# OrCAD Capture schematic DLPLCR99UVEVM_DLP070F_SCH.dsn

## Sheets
1 PG01 Title: size A3; rev: C
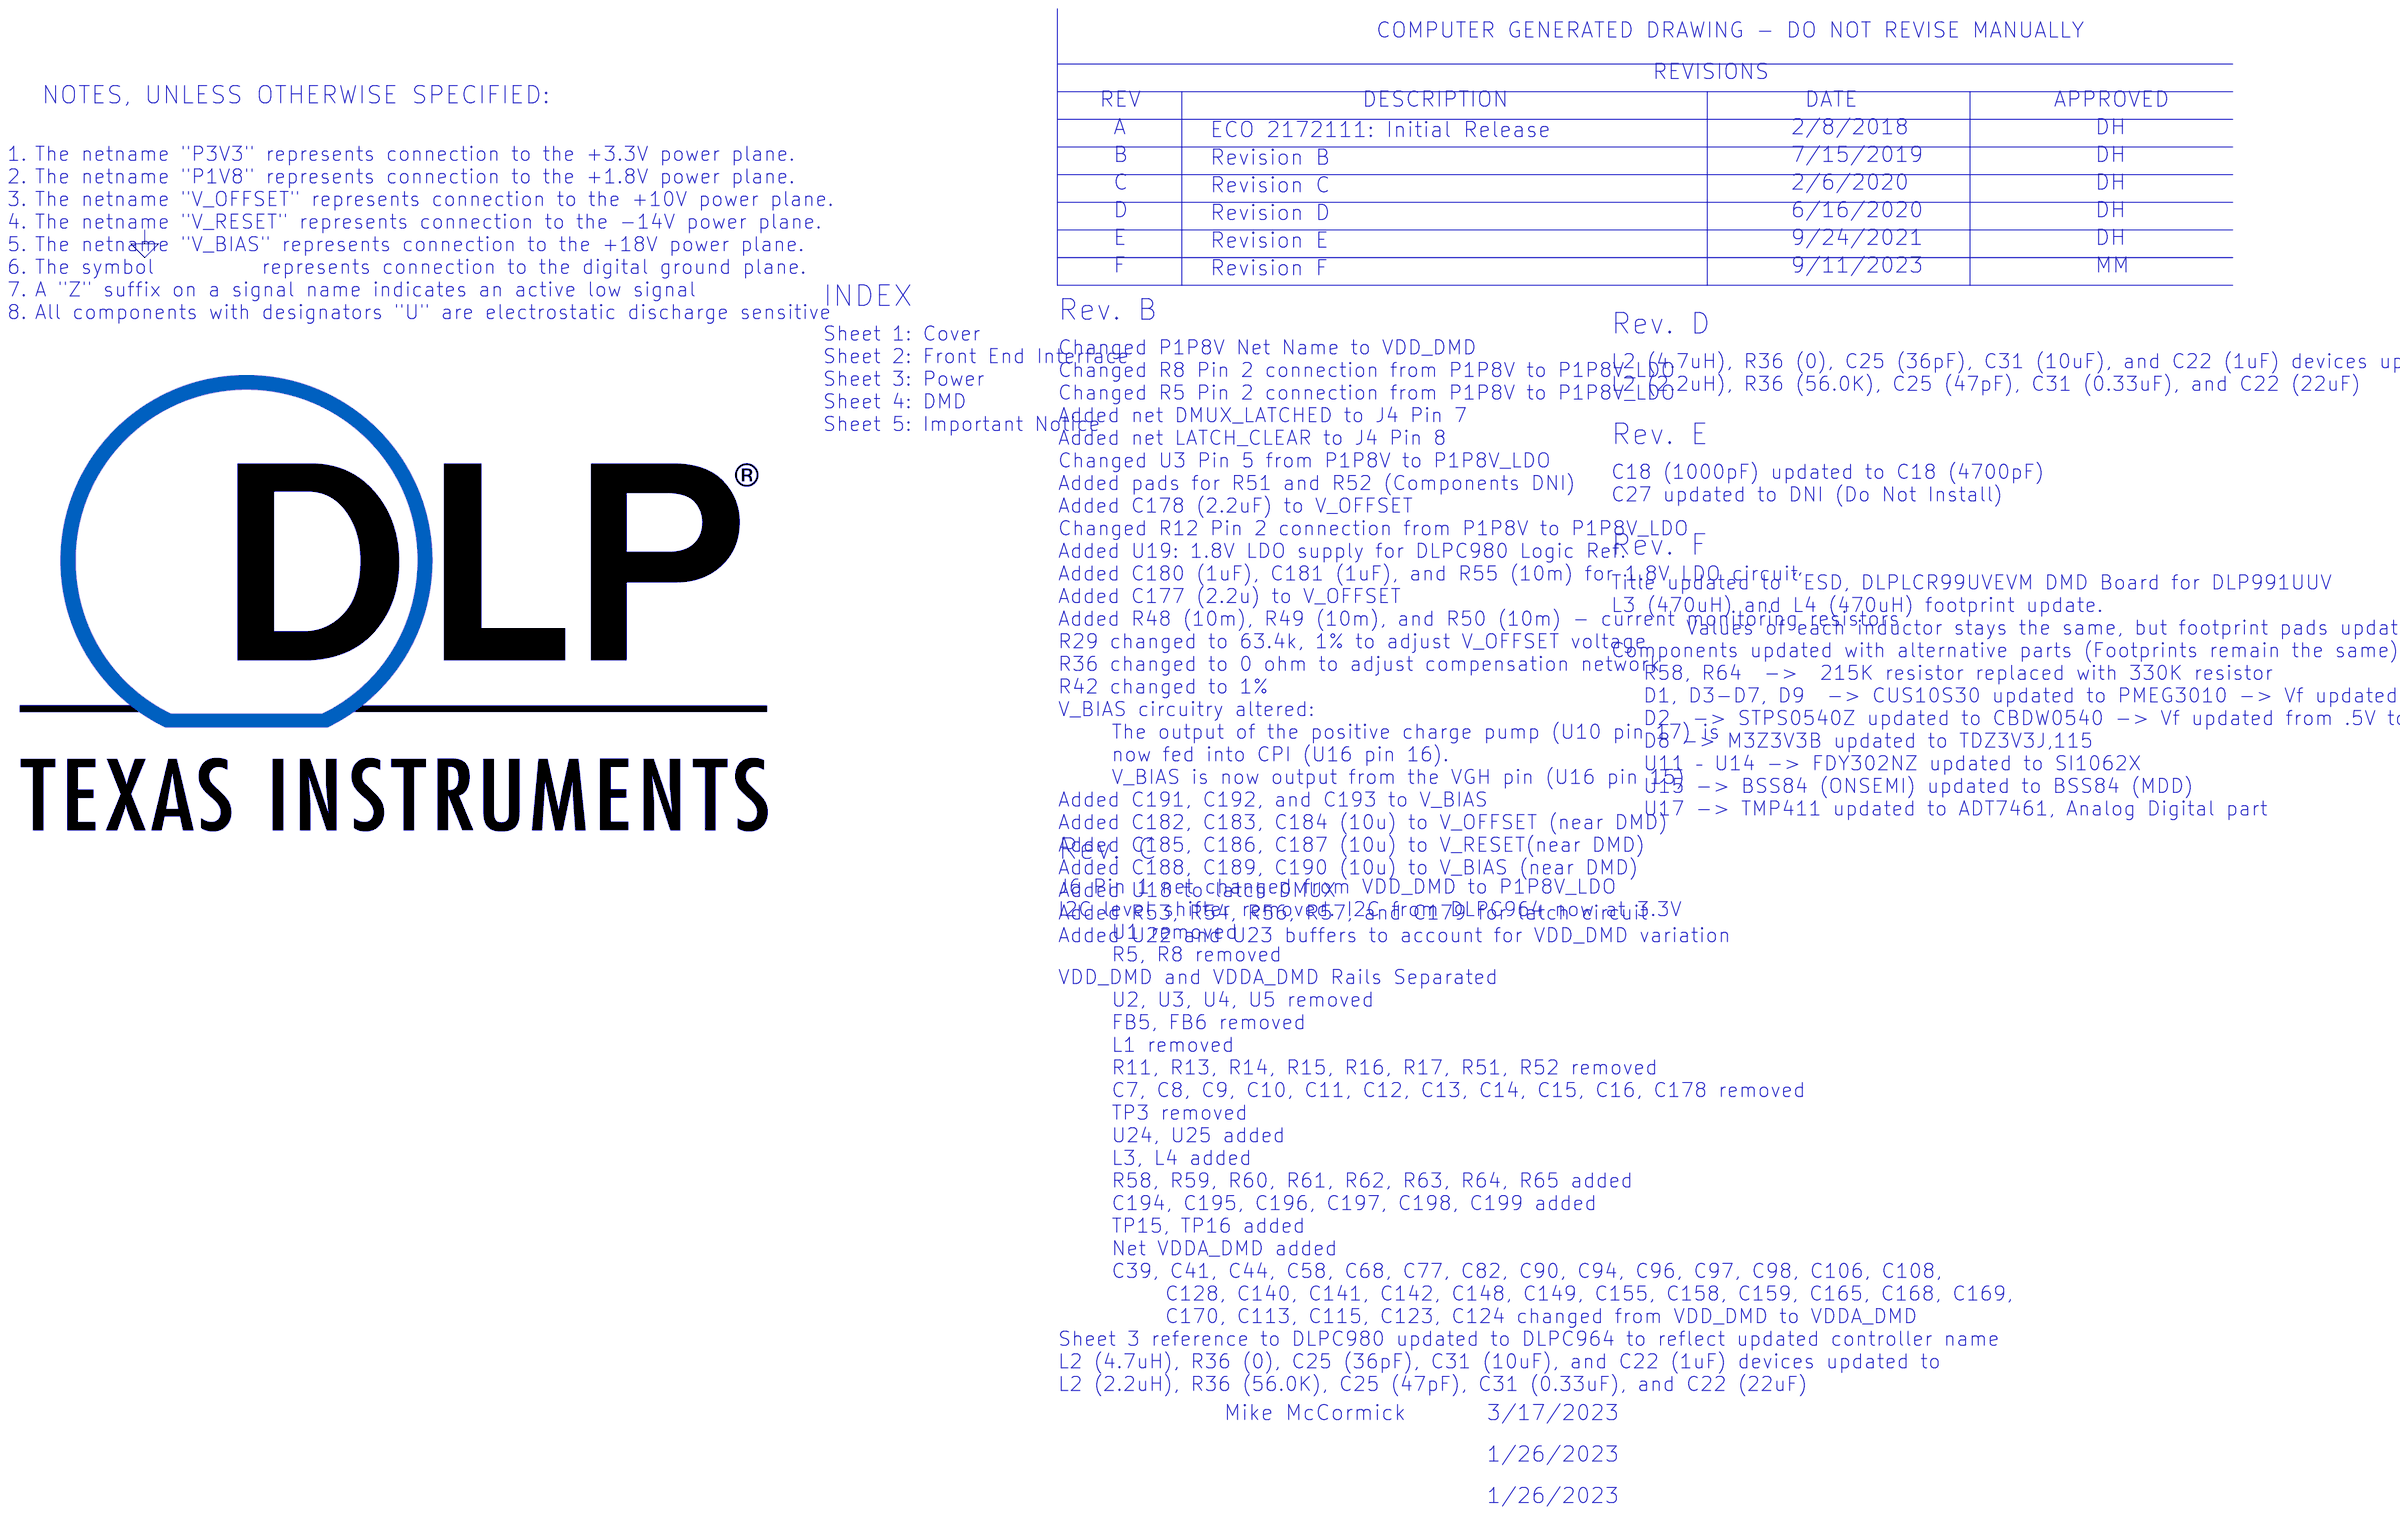
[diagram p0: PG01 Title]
2 PG02 Connectors: size A1
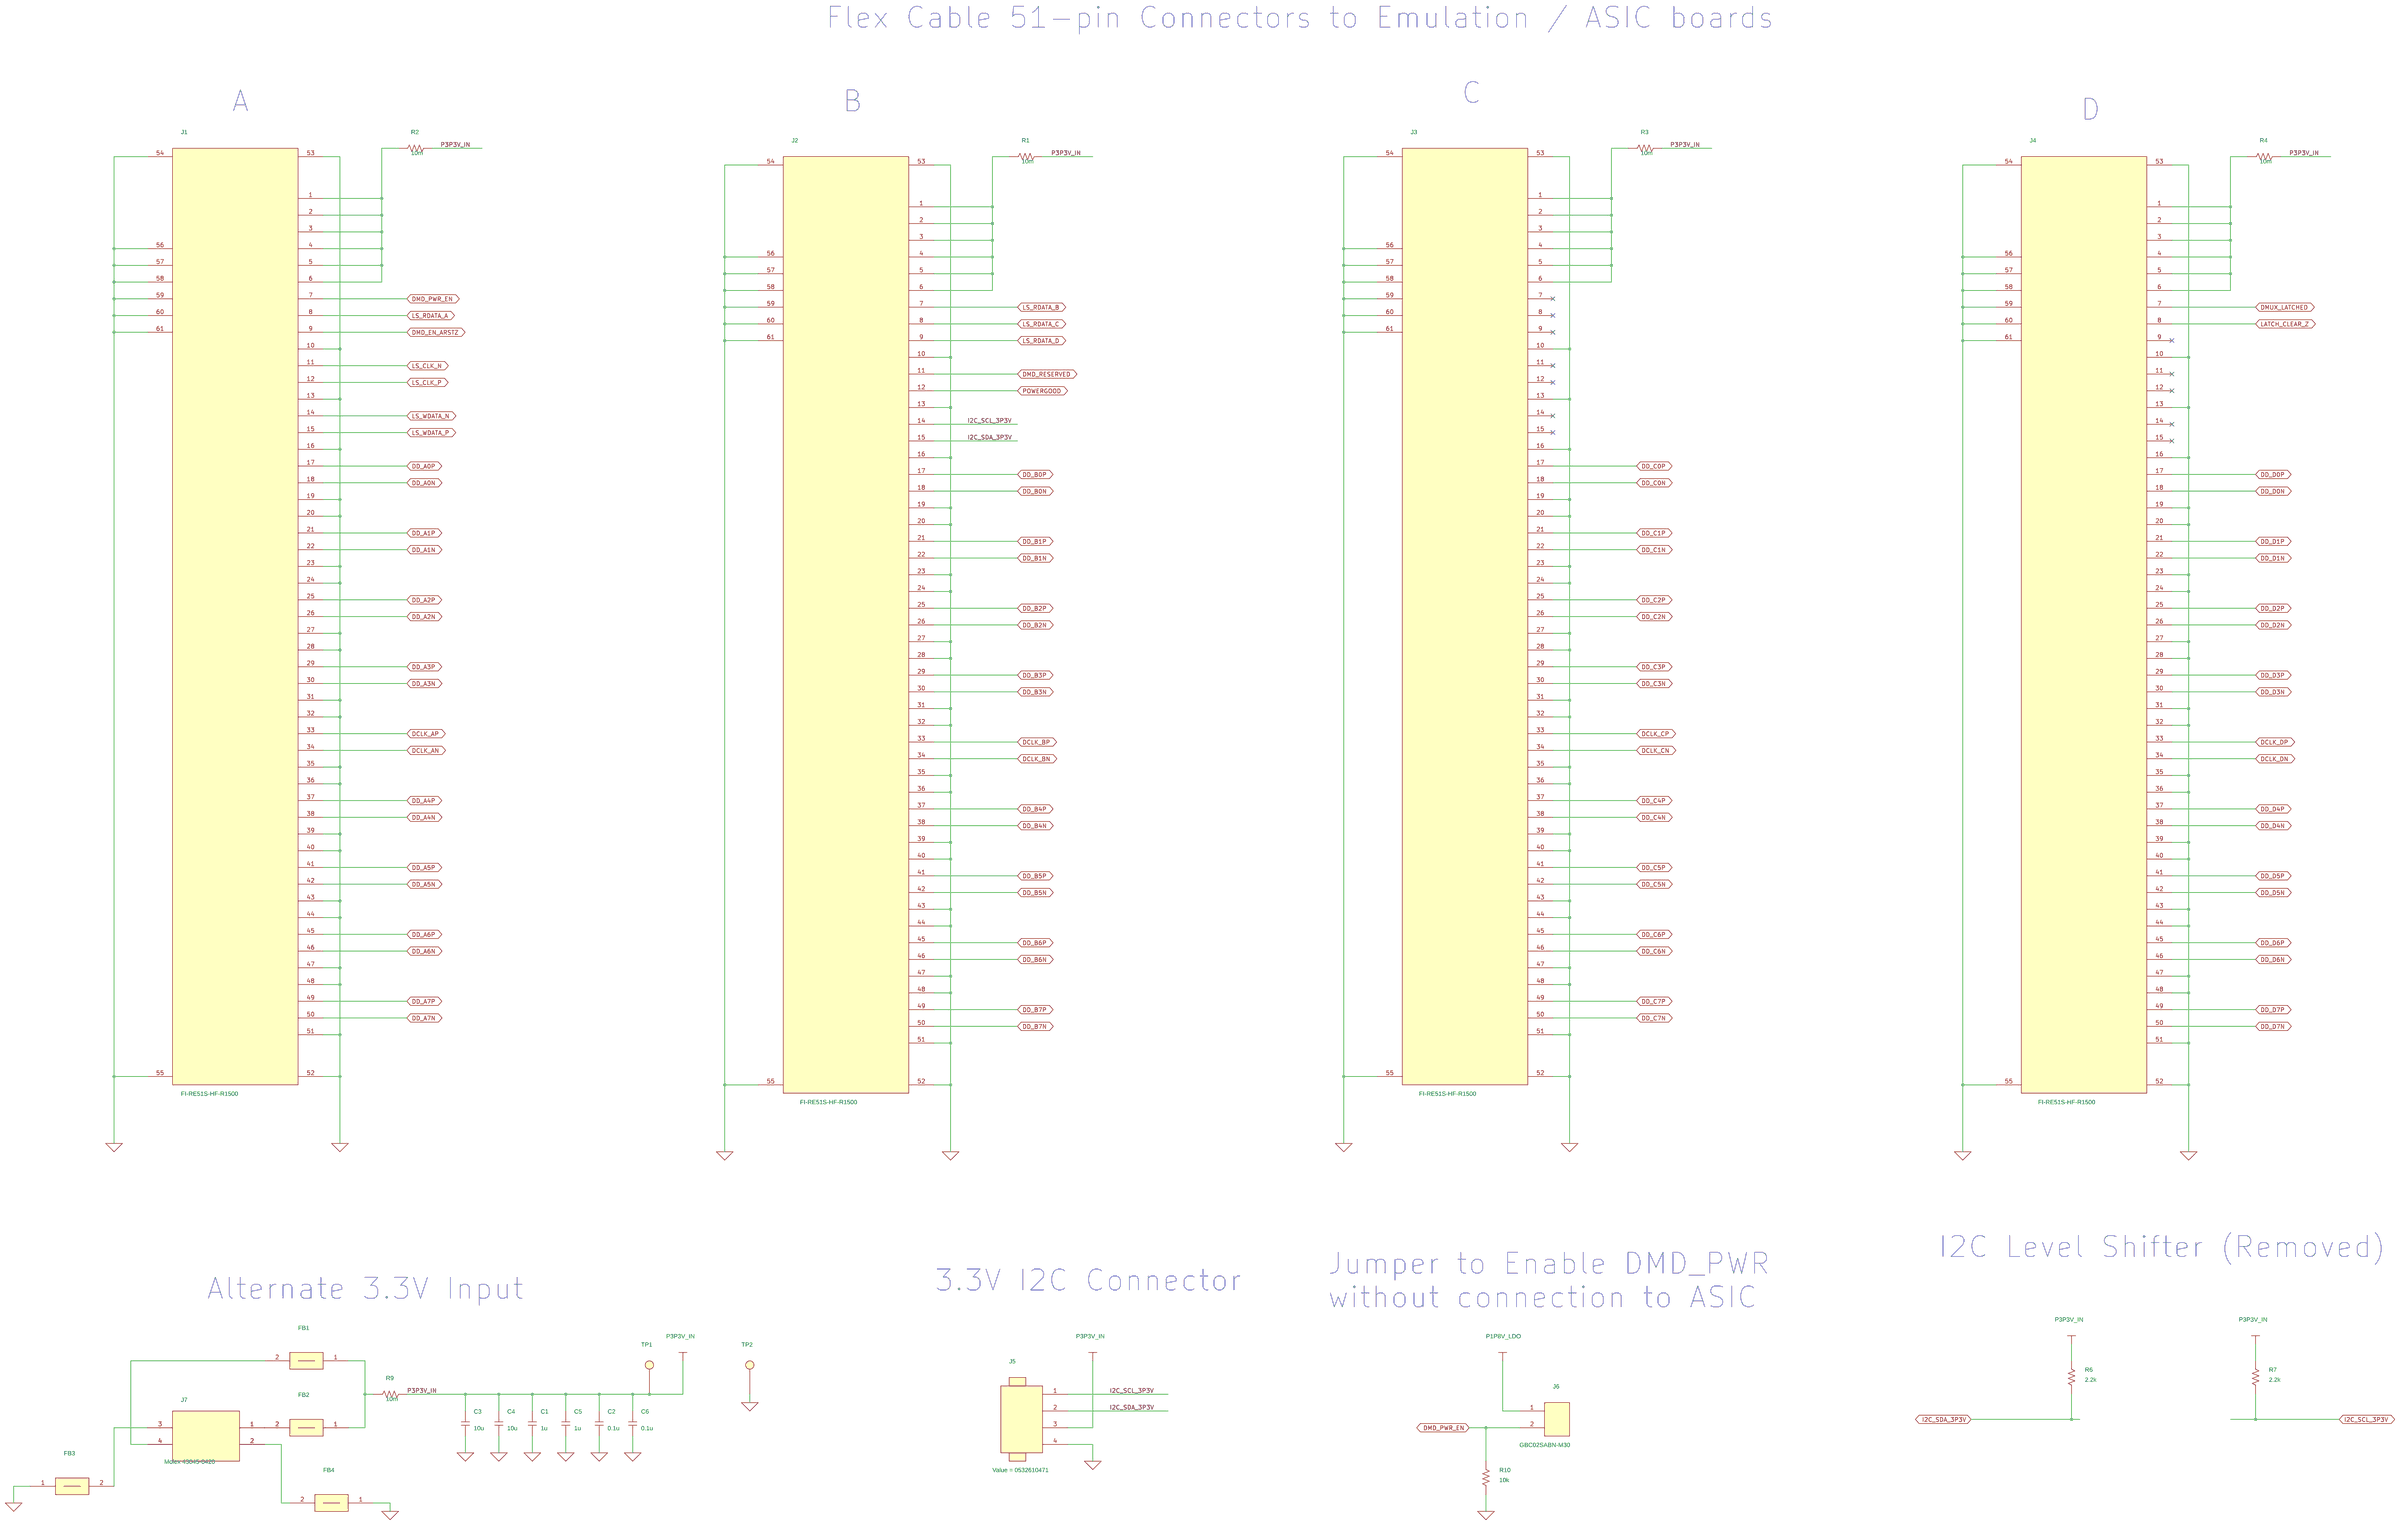
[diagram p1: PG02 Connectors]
3 PG03 Power: size A1
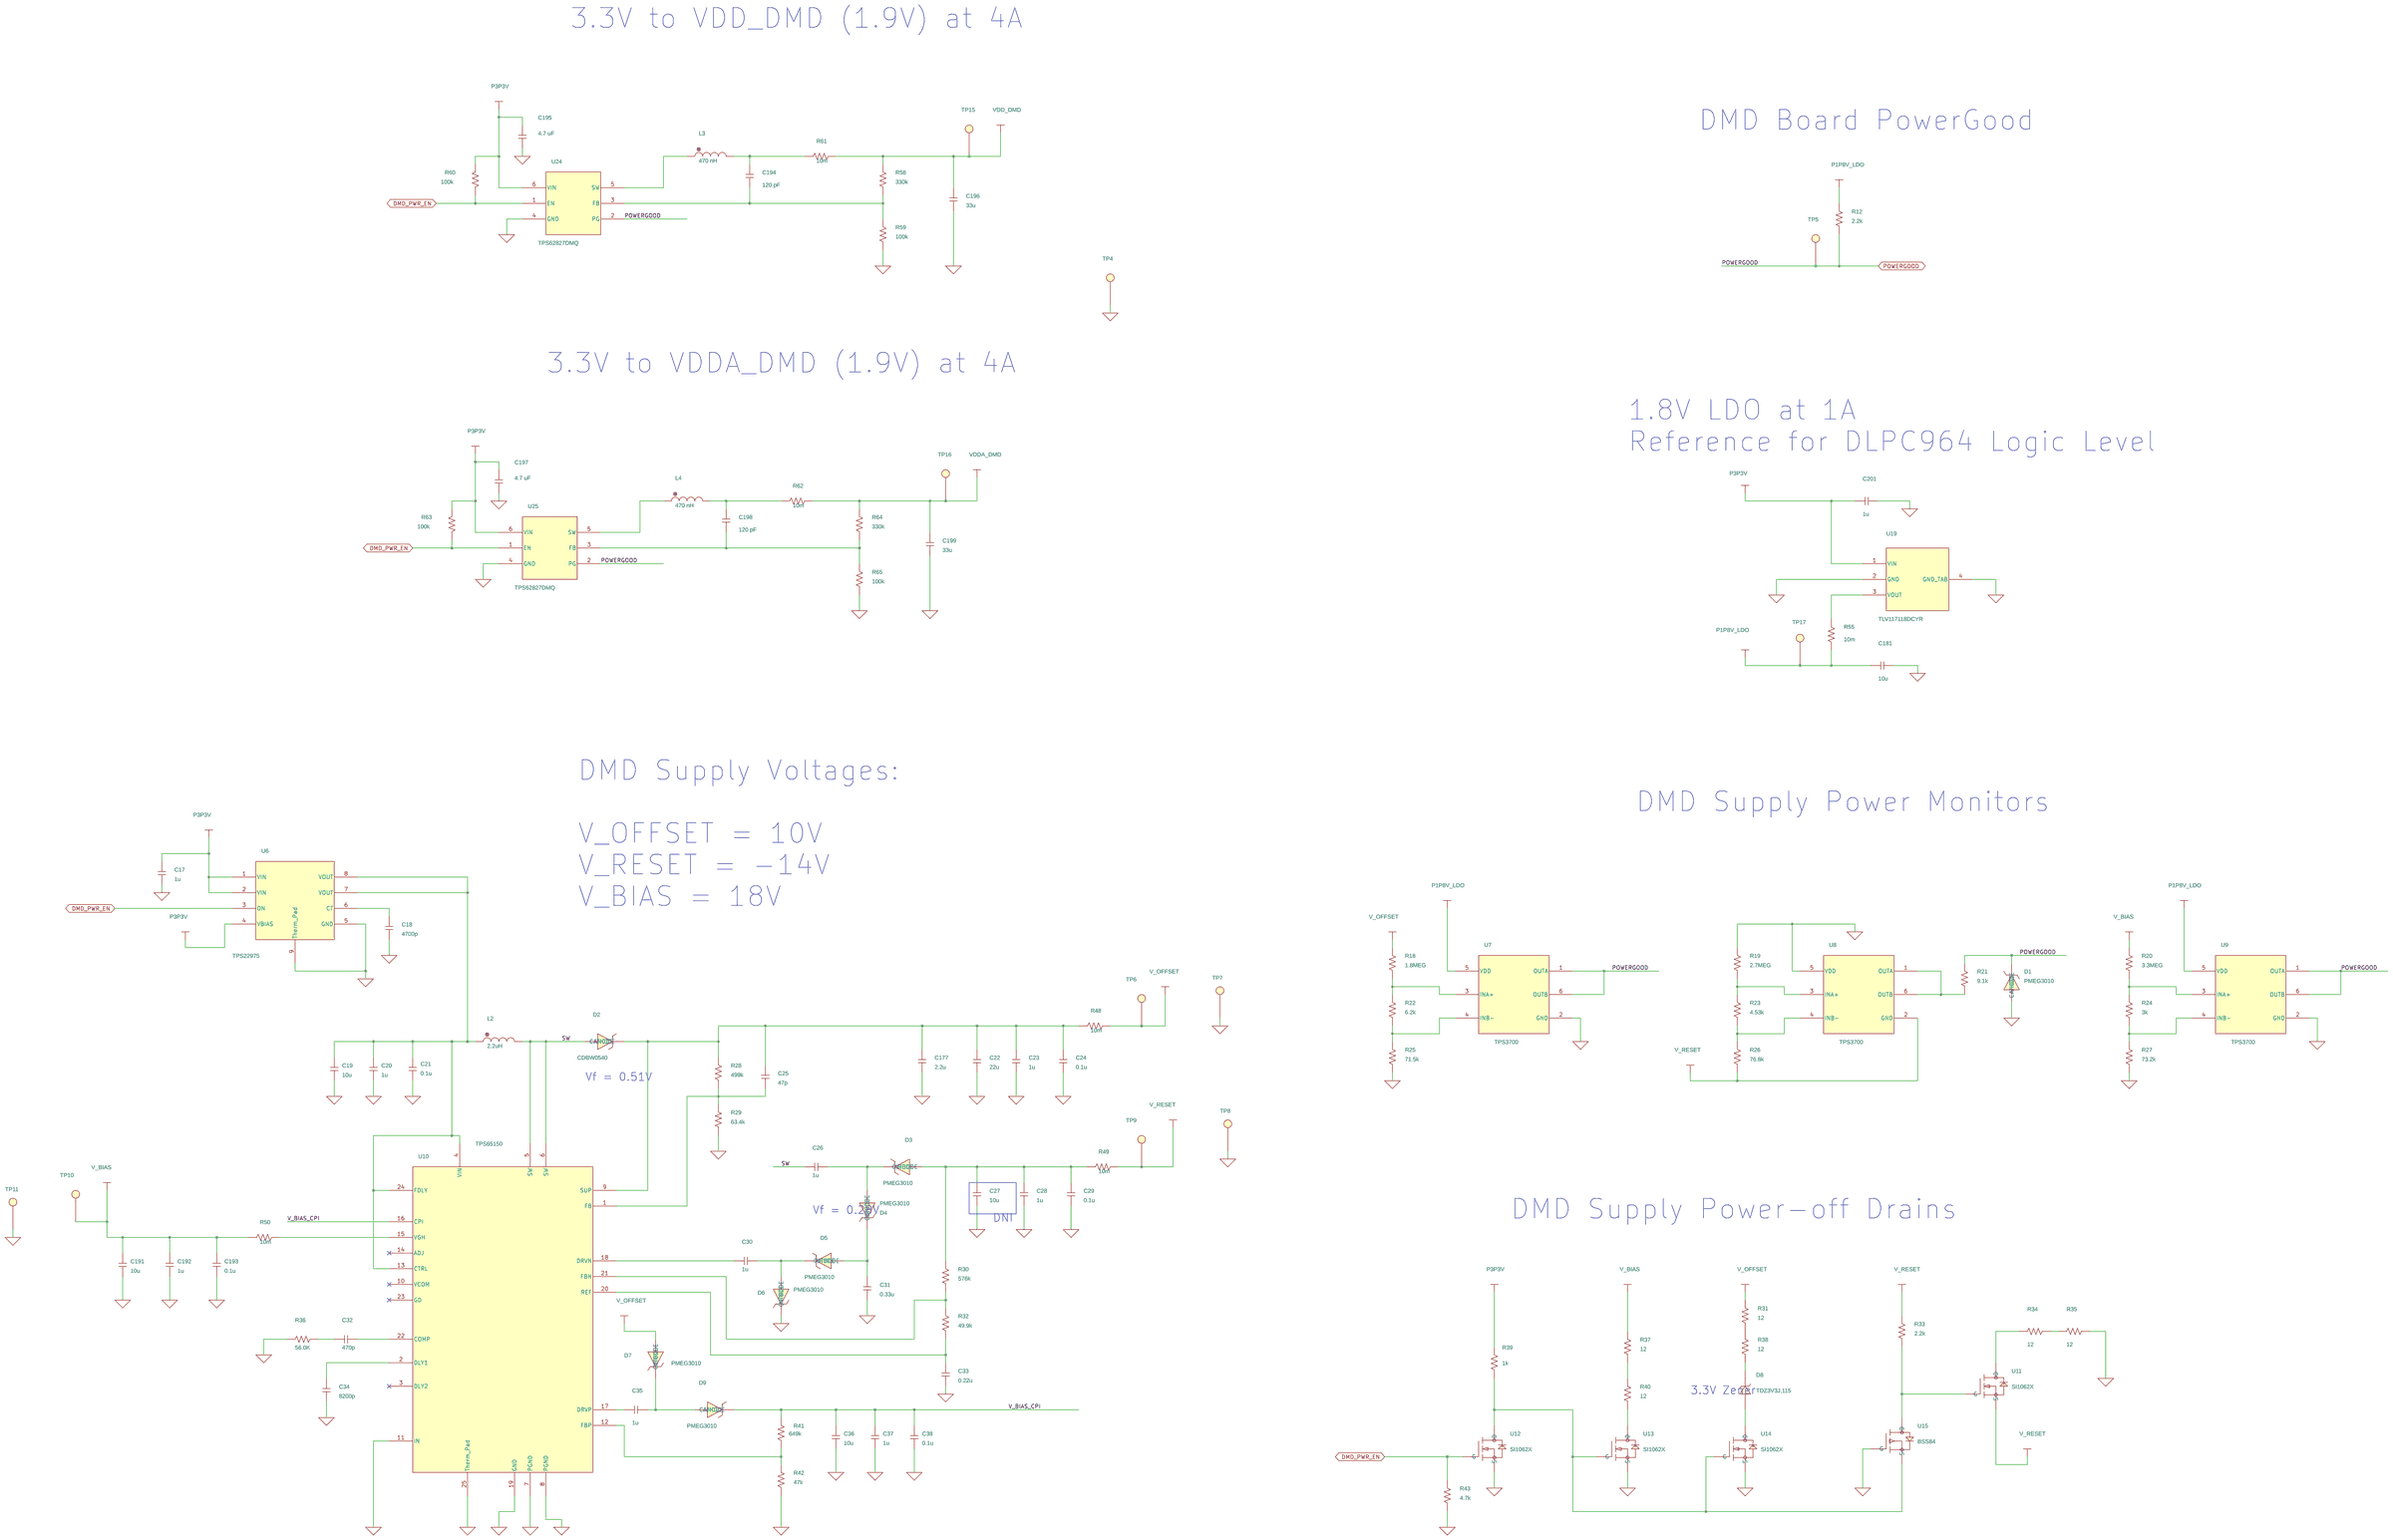
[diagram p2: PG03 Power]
4 PG04 DMD: size A1
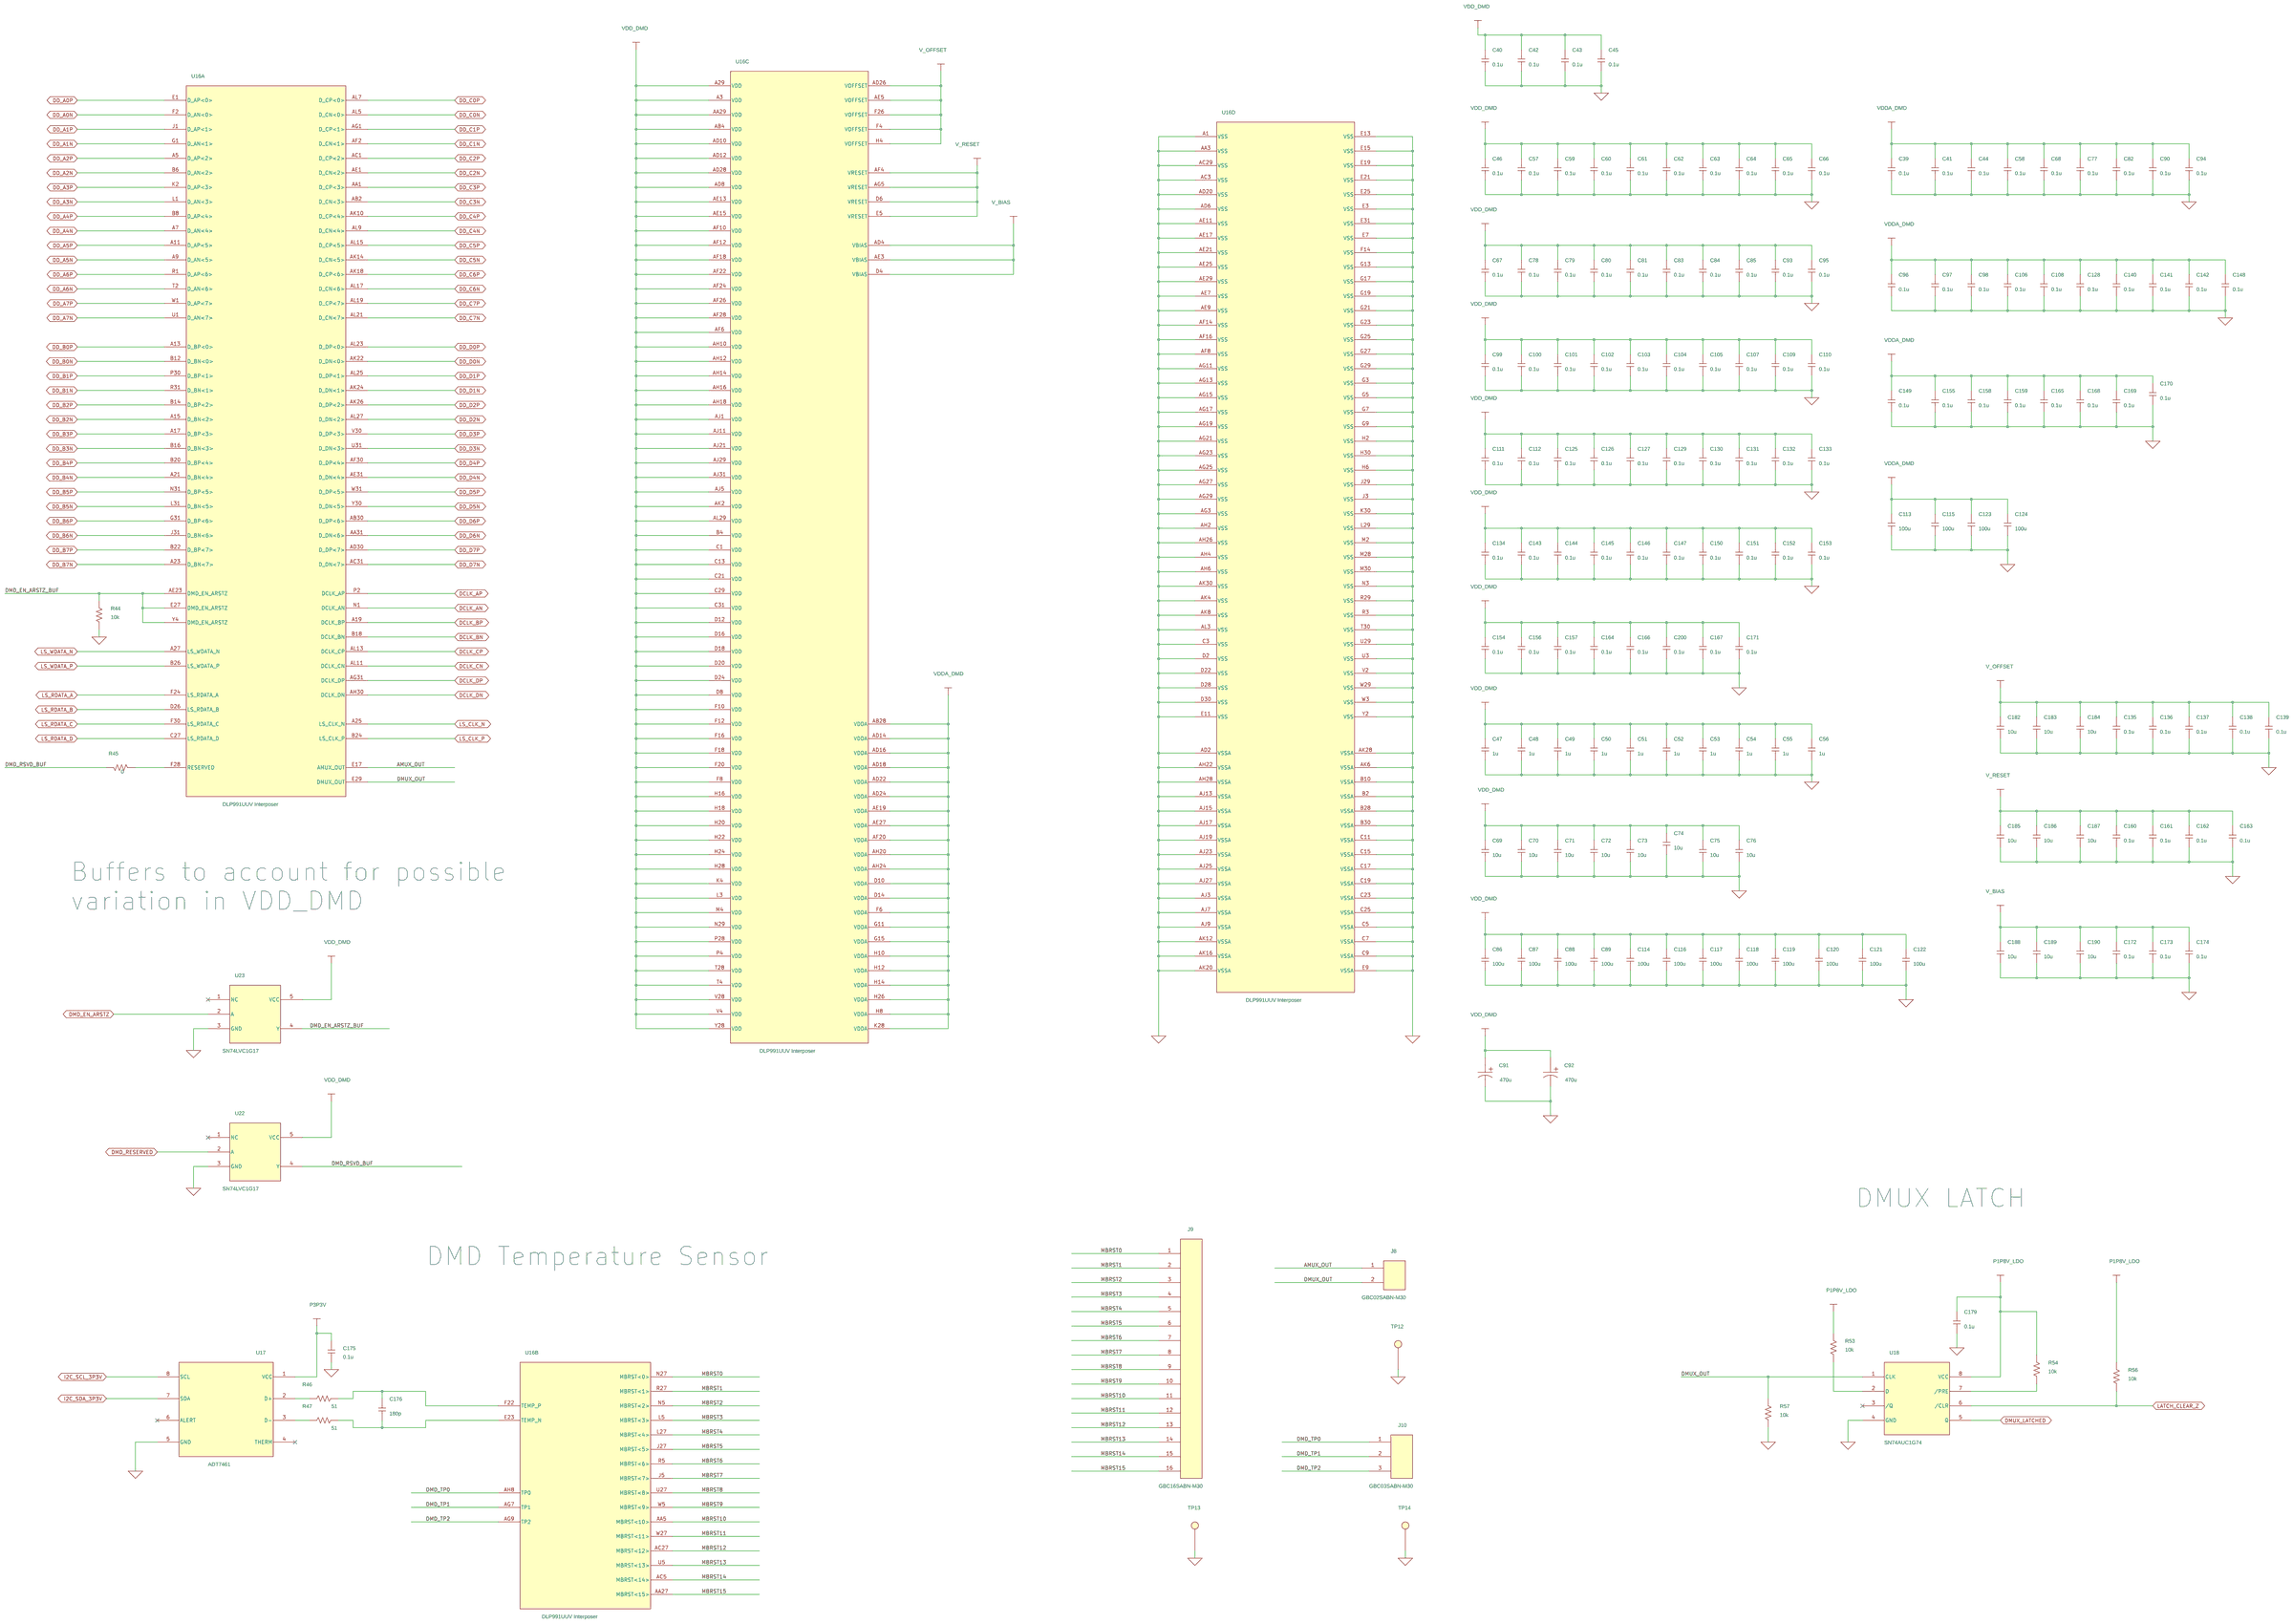
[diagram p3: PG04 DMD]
5 PG05 Important Notice
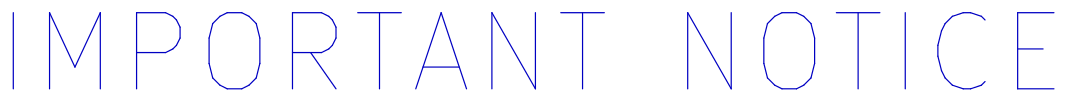
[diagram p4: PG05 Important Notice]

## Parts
sheet PG02 Connectors
C1  1u  [0402]
C2  0.1u  [0402]
C3  10u  [0603]
C4  10u  [0603]
C5  1u  [0402]
C6  0.1u  [0402]
FB1  FB  [1210]
FB2  FB  [1210]
FB3  FB  [1210]
FB4  FB  [1210]
J1  FI-RE51S-HF-R1500  [CONN51-FI-R_JAE]
J2  FI-RE51S-HF-R1500  [CONN51-FI-R_JAE]
J3  FI-RE51S-HF-R1500  [CONN51-FI-R_JAE]
J4  FI-RE51S-HF-R1500  [CONN51-FI-R_JAE]
J5  0532610471  [CONN4-53261-A_MOLEX]
J6  GBC02SABN-M30  [CONN2-GBC02SABN-M30_SUL]
J7  Molex 43045-0420  [CONN4-43045-0418_MLX]
R1  10m  [1206-WIDE-LTR18_ROHM]
R2  10m  [1206-WIDE-LTR18_ROHM]
R3  10m  [1206-WIDE-LTR18_ROHM]
R4  10m  [1206-WIDE-LTR18_ROHM]
R6  2.2k  [0402]
R7  2.2k  [0402]
R9  10m  [1206-WIDE-LTR18_ROHM]
R10  10k  [0402]
TP1  Testpoint  [TP-48RD]
TP2  GND Testpoint  [TP-5006-GND_KEY]
sheet PG03 Power
C17  1u  [0402]
C18  4700p  [0402]
C19  10u  [0603]
C20  1u  [0402]
C21  0.1u  [0402]
C22  22u  [0805]
C23  1u  [0402]
C24  0.1u  [0402]
C25  47p  [0402]
C26  1u  [0402]
C27  10u  [0603]
C28  1u  [0402]
C29  0.1u  [0402]
C30  1u  [0402]
C31  0.33u  [0402]
C32  470p  [0402]
C33  0.22u  [0402]
C34  8200p  [0402]
C35  1u  [0402]
C36  10u  [0603]
C37  1u  [0402]
C38  0.1u  [0402]
C177  2.2u  [0402]
C181  10u  [0603]
C191  10u  [0603]
C192  1u  [0402]
C193  0.1u  [0402]
C194  120 pF  [0402]
C195  4.7 uF  [0805]
C196  33u  [0805]
C197  4.7 uF  [0805]
C198  120 pF  [0402]
C199  33u  [0805]
C201  1u  [0402]
D1  PMEG3010  [SOD323-REV_MCC]
D2  CDBW0540  [SOD-123-STP-REV_ST]
D3  PMEG3010  [SOD323-REV_MCC]
D4  PMEG3010  [SOD323-REV_MCC]
D5  PMEG3010  [SOD323-REV_MCC]
D6  PMEG3010  [SOD323-REV_MCC]
D7  PMEG3010  [SOD323-REV_MCC]
D8  3.3V  [DIO-SOD323F_FC]
D9  PMEG3010  [SOD323-REV_MCC]
L2  2.2uH  [IND-SPM6530_TDK]
L3  470 nH  [IND_SPM5030VT]
L4  470 nH  [IND_SPM5030VT]
R12  2.2k  [0402]
R18  1.8MEG  [0402]
R19  2.7MEG  [0402]
R20  3.3MEG  [0402]
R21  9.1k  [0402]
R22  6.2k  [0402]
R23  4.53k  [0402]
R24  3k  [0402]
R25  71.5k  [0402]
R26  76.8k  [0402]
R27  73.2k  [0402]
R28  499k  [0402]
R29  63.4k  [0402]
R30  576k  [0402]
R31  12  [0402]
R32  49.9k  [0402]
R33  2.2k  [0402]
R34  12  [0402]
R35  12  [0402]
R36  56.0K  [0402]
R37  12  [0402]
R38  12  [0402]
R39  1k  [0402]
R40  12  [0402]
R41  649k  [0402]
R42  47k  [0402]
R43  4.7k  [0402]
R48  10m  [1206-WIDE-LTR18_ROHM]
R49  10m  [1206-WIDE-LTR18_ROHM]
R50  10m  [1206-WIDE-LTR18_ROHM]
R55  10m  [1206-WIDE-LTR18_ROHM]
R58  330k  [0603]
R59  100k  [0603]
R60  100k  [0603]
R61  10m  [1206-WIDE-LTR18_ROHM]
R62  10m  [1206-WIDE-LTR18_ROHM]
R63  100k  [0603]
R64  330k  [0603]
R65  100k  [0603]
TP4  GND Testpoint  [TP-5006-GND_KEY]
TP5  Testpoint  [TP-48RD]
TP6  Testpoint  [TP-48RD]
TP7  GND Testpoint  [TP-5006-GND_KEY]
TP8  GND Testpoint  [TP-5006-GND_KEY]
TP9  Testpoint  [TP-48RD]
TP10  Testpoint  [TP-48RD]
TP11  GND Testpoint  [TP-5006-GND_KEY]
TP15  GND Testpoint  [TP-5006-GND_KEY]
TP16  GND Testpoint  [TP-5006-GND_KEY]
TP17  GND Testpoint  [TP-5006-GND_KEY]
U6  TPS22975  [SOIC8-DSG_TI]
U7  TPS3700  [SOIC6-DDC_TI]
U8  TPS3700  [SOIC6-DDC_TI]
U9  TPS3700  [SOIC6-DDC_TI]
U10  TPS65150  [SOIC24-PWP_TI_A]
U11  SI1062X  [SOT-490-SC89-3_FC]
U12  SI1062X  [SOT-490-SC89-3_FC]
U13  SI1062X  [SOT-490-SC89-3_FC]
U14  SI1062X  [SOT-490-SC89-3_FC]
U15  BSS84  [SOT23-3_FC]
U19  TLV117118DCYR  [SOT223AVX]
U24  TPS62827DMQ  [SOIC6-VSON-HR-DMQ_TI]
U25  TPS62827DMQ  [SOIC6-VSON-HR-DMQ_TI]
sheet PG04 DMD
C39  0.1u  [0402]
C40  0.1u  [0402]
C41  0.1u  [0402]
C42  0.1u  [0402]
C43  0.1u  [0402]
C44  0.1u  [0402]
C45  0.1u  [0402]
C46  0.1u  [0402]
C47  1u  [0402]
C48  1u  [0402]
C49  1u  [0402]
C50  1u  [0402]
C51  1u  [0402]
C52  1u  [0402]
C53  1u  [0402]
C54  1u  [0402]
C55  1u  [0402]
C56  1u  [0402]
C57  0.1u  [0402]
C58  0.1u  [0402]
C59  0.1u  [0402]
C60  0.1u  [0402]
C61  0.1u  [0402]
C62  0.1u  [0402]
C63  0.1u  [0402]
C64  0.1u  [0402]
C65  0.1u  [0402]
C66  0.1u  [0402]
C67  0.1u  [0402]
C68  0.1u  [0402]
C69  10u  [0603]
C70  10u  [0603]
C71  10u  [0603]
C72  10u  [0603]
C73  10u  [0603]
C74  10u  [0603]
C75  10u  [0603]
C76  10u  [0603]
C77  0.1u  [0402]
C78  0.1u  [0402]
C79  0.1u  [0402]
C80  0.1u  [0402]
C81  0.1u  [0402]
C82  0.1u  [0402]
C83  0.1u  [0402]
C84  0.1u  [0402]
C85  0.1u  [0402]
C86  100u  [1210]
C87  100u  [1210]
C88  100u  [1210]
C89  100u  [1210]
C90  0.1u  [0402]
C91  470u  [CAP2-146CTI-1213_VISHAY]
C92  470u  [CAP2-146CTI-1213_VISHAY]
C93  0.1u  [0402]
C94  0.1u  [0402]
C95  0.1u  [0402]
C96  0.1u  [0402]
C97  0.1u  [0402]
C98  0.1u  [0402]
C99  0.1u  [0402]
C100  0.1u  [0402]
C101  0.1u  [0402]
C102  0.1u  [0402]
C103  0.1u  [0402]
C104  0.1u  [0402]
C105  0.1u  [0402]
C106  0.1u  [0402]
C107  0.1u  [0402]
C108  0.1u  [0402]
C109  0.1u  [0402]
C110  0.1u  [0402]
C111  0.1u  [0402]
C112  0.1u  [0402]
C113  100u  [1210]
C114  100u  [1210]
C115  100u  [1210]
C116  100u  [1210]
C117  100u  [1210]
C118  100u  [1210]
C119  100u  [1210]
C120  100u  [1210]
C121  100u  [1210]
C122  100u  [1210]
C123  100u  [1210]
C124  100u  [1210]
C125  0.1u  [0402]
C126  0.1u  [0402]
C127  0.1u  [0402]
C128  0.1u  [0402]
C129  0.1u  [0402]
C130  0.1u  [0402]
C131  0.1u  [0402]
C132  0.1u  [0402]
C133  0.1u  [0402]
C134  0.1u  [0402]
C135  0.1u  [0402]
C136  0.1u  [0402]
C137  0.1u  [0402]
C138  0.1u  [0402]
C139  0.1u  [0402]
C140  0.1u  [0402]
C141  0.1u  [0402]
C142  0.1u  [0402]
C143  0.1u  [0402]
C144  0.1u  [0402]
C145  0.1u  [0402]
C146  0.1u  [0402]
C147  0.1u  [0402]
C148  0.1u  [0402]
C149  0.1u  [0402]
C150  0.1u  [0402]
C151  0.1u  [0402]
C152  0.1u  [0402]
C153  0.1u  [0402]
C154  0.1u  [0402]
C155  0.1u  [0402]
C156  0.1u  [0402]
C157  0.1u  [0402]
C158  0.1u  [0402]
C159  0.1u  [0402]
C160  0.1u  [0402]
C161  0.1u  [0402]
C162  0.1u  [0402]
C163  0.1u  [0402]
C164  0.1u  [0402]
C165  0.1u  [0402]
C166  0.1u  [0402]
C167  0.1u  [0402]
C168  0.1u  [0402]
C169  0.1u  [0402]
C170  0.1u  [0402]
C171  0.1u  [0402]
C172  0.1u  [0402]
C173  0.1u  [0402]
C174  0.1u  [0402]
C175  0.1u  [0402]
C176  180p  [0402]
C179  0.1u  [0402]
C182  10u  [0603]
C183  10u  [0603]
C184  10u  [0603]
C185  10u  [0603]
C186  10u  [0603]
C187  10u  [0603]
C188  10u  [0603]
C189  10u  [0603]
C190  10u  [0603]
C200  0.1u  [0402]
J8  GBC02SABN-M30  [CONN2-GBC02SABN-M30_SUL]
J9  GBC16SABN-M30  [CONN16-GBC16SABN-M30_SUL]
J10  GBC03SABN-M30  [CONN3-GBC03SABN-M30_SUL]
R44  10k  [0402]
R45  0  [0402]
R46  51  [0603]
R47  51  [0603]
R53  10k  [0402]
R54  10k  [0402]
R56  10k  [0402]
R57  10k  [0402]
TP12  GND Testpoint  [TP-5006-GND_KEY]
TP13  GND Testpoint  [TP-5006-GND_KEY]
TP14  GND Testpoint  [TP-5006-GND_KEY]
U16  DLP991UUV Interposer  [DMD-98-DC4K-TRP-FLRA_TI]  (sections A,B,C,D)
U17  ADT7461  [SOIC8-DGK_TI]
U18  SN74AUC1G74  [SOIC8-DCU_TI]
U22  SN74LVC1G17  [SOIC5-SOT-23_DBV-TI]
U23  SN74LVC1G17  [SOIC5-SOT-23_DBV-TI]

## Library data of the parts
C1 C5 C17 C20 C23 C26 C28 C30 C35 C37 C47-C56 C192 C201 = C: DigiKey Part Number: Mouser  81-GRM155R6YA105KE1D; MFG: Murata; PART NUMBER: GRM155R6YA105KE11D; TOLERANCE: 10%; VOLTAGE: 35V
C2 C6 C21 C24 C29 C38-C46 C57-C68 C77-C85 C90 C93-C112 C125-C175 C179 C193 C200 = C: DigiKey Part Number: 445-6899-1-ND; MFG: TDK; PART NUMBER: CGA2B3X7R1H104K050BB; TOLERANCE: 10%; VOLTAGE: 50V
C3 C4 C19 C36 C69-C76 C181-C191 = C: DigiKey Part Number: 445-9015-1-ND; MFG: TDK; PART NUMBER: C1608X5R1E106M080AC; TOLERANCE: 20%; VOLTAGE: 25V
FB1-FB4 = Ferrite_Bead_1: DigiKey Part Number: 490-9566-1-ND; MFG: Murata; PART NUMBER: BLE32PN300SN1L
J1-J4 = FI-RE51S-VF-R1300: DigiKey Part Number: 670-1206-1-ND; MFG: JAE
J5 = Conn_4: Connector, 4 Pin; DigiKey Part Number: WM7622CT-ND; MFG: Molex; Part Number: 053261-0471
J6 J8 = 2x1_Header: DigiKey Part Number: S1033E-02-ND; MFG: Sullins
J7 = Molex_43045-0418_0: DigiKey Part Number: WM2661CT-ND; MFG: Molex; PART NUMBER: 0430450419
R1-R4 R9 R48-R50 R55 R61 R62 = R: DigiKey Part Number: RHM1227CT-ND; MFG: Rohm; PART NUMBER: LTR18EZPFU10L0
R6 R7 R12 R33 = R: DigiKey Part Number: P2.2KJCT-ND; MFG: Panasonic; PART NUMBER: ERJ-2GEJ222X; POWER: 1/10 W; TOLERANCE: 5%
R10 R44 R53 R54 R56 R57 = R: DigiKey Part Number: 1276-3431-1-ND; MFG: Samsung; PART NUMBER: RC1005F103CS; POWER: 1/16 W; TOLERANCE: 1%
TP1 TP5 TP6 TP9 TP10 = Testpoint: MFG: NOT-A-PART; PART NUMBER: NOT-A-PART
TP2 TP4 TP7 TP8 TP11-TP17 = Testpoint: DigiKey Part Number: 36-5006-ND; MFG: Keystone; PART NUMBER: 5006
C18 = C: DigiKey Part Number: 1276-6576-1-ND; MFG: Samsung; PART NUMBER: CL05B472KB5VPNC; TOLERANCE: 10%; VOLTAGE: 50V
C22 = C: DigiKey Part Number: 445-14428-1-ND; MFG: TDK; PART NUMBER: C2012X5R1V226M125AC; TOLERANCE: 20%; VOLTAGE: 35V
C25 = C: DigiKey Part Number: 311-1021-1-ND; MFG: Yageo; PART NUMBER: CC0402JRNPO9BN470; TOLERANCE: 5%; VOLTAGE: 50V
C27 = C: DigiKey Part Number: ChipOneStop C1S741000950158; MFG: TDK; Notes: DNI; PART NUMBER: C1608X5R1E106M080AC; TOLERANCE: 20%; VOLTAGE: 25V
C31 = C: DigiKey Part Number: 445-180203-1-ND; MFG: TDK; PART NUMBER: CGA2B1X7S1C334K050BC; TOLERANCE: 10%; VOLTAGE: 16V
C32 = C: DigiKey Part Number: 1276-1566-1-ND; MFG: Samsung; PART NUMBER: CL05B471KB5NNNC; TOLERANCE: 10%; VOLTAGE: 50V
C33 = C: DigiKey Part Number: 490-12246-1-ND; MFG: Murata; PART NUMBER: GRT155C81E224ME01D; TOLERANCE: 20%; VOLTAGE: 25V
C34 = C: DigiKey Part Number: 399-3075-1-ND; MFG: KEMET; PART NUMBER: C0402C822K5RACTU; TOLERANCE: 10%; VOLTAGE: 50V
C177 = C: DigiKey Part Number: 445-9028-1-ND; MFG: TDK; PART NUMBER: C1005X5R1V225K050BC; TOLERANCE: 10%; VOLTAGE: 35V
C194 C198 = C: DigiKey Part Number: 445-6899-1-ND; MFG: Samsung; PART NUMBER: CL05C121JB5NNNC; Rating: 50 V; TOLERANCE: 5%; VOLTAGE: 50V
C195 C197 = C: DigiKey Part Number: 445-6899-1-ND; MFG: Samsung; PART NUMBER: CL21B475KAFNNNE; Rating: 25 V; TOLERANCE: 10%; VOLTAGE: 50V
C196 C199 = C: DigiKey Part Number: 445-5986-1-ND; MFG: TDK; PART NUMBER: C2012X5R0J336M125AC; TOLERANCE: 20%; VOLTAGE: 6.3V
D1 D3-D7 D9 = DIODE_SCHOTTKY_dsize: Diode Schottky; DigiKey Part Number: 1727-5199-1-ND; Mfg: Nexperia; Part Number: PMEG3010BEA,115; Rating: 40V 0.5A
D2 = DIODE_SCHOTTKY_dsize: Diode Schottky; DigiKey Part Number: 641-1327-1-ND; Mfg: Comchip Technology; Part Number: CDBW0540-G; Rating: 40V 0.5A
D8 = DIODE_ZENER: Diode, Zener; DigiKey Part Number: 1727-1757-1-ND; Mfg: Nexperia; Part Number: TDZ3V3J,115
L2 = L: CURRENT: 8.2A; DigiKey Part Number: 445-4118-1-ND; MFG: TDK; PART NUMBER: SPM6530T-2R2M; TOLERANCE: 20%
L3 L4 = L: CURRENT: 12.9A; DigiKey Part Number: 445-SPM5030VT-R47M-DCT-ND; MFG: TDK; PART NUMBER: SPM5030VT-R47M-D; Rating: 6.7 A; TOLERANCE: 20%
R18 = R: DigiKey Part Number: P1.8MJCT-ND; MFG: Panasonic; PART NUMBER: ERJ-2GEJ185X; POWER: 1/10 W; TOLERANCE: 5%
R19 = R: DigiKey Part Number: P2.7MJCT-ND; MFG: Panasonic; PART NUMBER: ERJ-2GEJ275X; POWER: 1/10 W; TOLERANCE: 5%
R20 = R: DigiKey Part Number: 311-3.30MLRCT-ND; MFG: Yageo; PART NUMBER: RC0402FR-073M3L; POWER: 1/16 W; TOLERANCE: 1%
R21 = R: DigiKey Part Number: P9.1KJCT-ND; MFG: Panasonic; PART NUMBER: ERJ-2GEJ912X; POWER: 1/10 W; TOLERANCE: 1%
R22 = R: DigiKey Part Number: P6.2KJCT-ND; MFG: Panasonic; PART NUMBER: ERJ-2GEJ622X; POWER: 1/10 W; TOLERANCE: 5%
R23 = R: DigiKey Part Number: P4.53KLCT-ND; MFG: Panasonic; PART NUMBER: ERJ-2RKF4531X; POWER: 1/10 W; TOLERANCE: 1%
R24 = R: DigiKey Part Number: P3.0KJCT-ND; MFG: Panasonic; PART NUMBER: ERJ-2GEJ302X; POWER: 1/10 W; TOLERANCE: 5%
R25 = R: DigiKey Part Number: P71.5KLCT-ND; MFG: Panasonic; PART NUMBER: ERJ-2RKF7152X; POWER: 1/10 W; TOLERANCE: 1%
R26 = R: DigiKey Part Number: P76.8KLCT-ND; MFG: Panasonic; PART NUMBER: ERJ-2RKF7682X; POWER: 1/10 W; TOLERANCE: 1%
R27 = R: DigiKey Part Number: P73.2KLCT-ND; MFG: Panasonic; PART NUMBER: ERJ-2RKF7322X; POWER: 1/10 W; TOLERANCE: 1%
R28 = R: DigiKey Part Number: 311-499KLRCT-ND; MFG: Yageo; PART NUMBER: RC0402FR-07499KL; POWER: 1/16 W; TOLERANCE: 1%
R29 = R: DigiKey Part Number: P63.4KLCT-ND; MFG: Panasonic; PART NUMBER: ERJ-2RKF6342X; POWER: 1/10 W; TOLERANCE: 1%
R30 = R: DigiKey Part Number: P576KLCT-ND; MFG: Panasonic; PART NUMBER: ERJ-2RKF5763X; POWER: 1/10 W; TOLERANCE: 1%
R31 R34 R35 R37 R38 R40 = R: DigiKey Part Number: P12JCT-ND; MFG: Panasonic; PART NUMBER: ERJ-2GEJ120X; POWER: 1/10 W; TOLERANCE: 5%
R32 = R: DigiKey Part Number: P49.9KLCT-ND; MFG: Panasonic; PART NUMBER: ERJ-2RKF4992X; POWER: 1/10 W; TOLERANCE: 1%
R36 = R: DigiKey Part Number: P56.0KLCT-ND; MFG: Panasonic; PART NUMBER: ERJ-2RKF5602X; TOLERANCE: 1%
R39 = R: DigiKey Part Number: P17193CT-ND; MFG: Panasonic; PART NUMBER: ERJ-PA2J102X; POWER: 1/5 W; TOLERANCE: 5%
R41 = R: DigiKey Part Number: P649KLCT-ND; MFG: Panasonic; PART NUMBER: ERJ-2RKF6493X; POWER: 1/10 W; TOLERANCE: 1%
R42 = R: DigiKey Part Number: P47.0KLCT-ND; MFG: Panasonic; PART NUMBER: ERJ-2RKF4702X; POWER: 1/10 W; TOLERANCE: 1%
R43 = R: DigiKey Part Number: 1276-4392-1-ND; MFG: Samsung; PART NUMBER: RC1005J472CS; POWER: 1/16 W; TOLERANCE: 5%
R58 R64 = R: DigiKey Part Number: 2679-TFCR0603-16W-E-3303DT-1KTR-ND; MFG: Venkel; PART NUMBER: TFCR0603-16W-E-3303DT-1K; Rating: 0.063 W; TOLERANCE: 0.5%
R59 R60 R63 R65 = R: DigiKey Part Number: 1276-3431-1-ND; MFG: Samsung; PART NUMBER: ERA-3AEB104V; Rating: 0.1 W; TOLERANCE: 0.1%
U6 = TPS22967_4: DigiKey Part Number: 296-47228-1-ND; MFG: Texas Instruments; PART NUMBER: TPS22975DSGR
U7-U9 = TPS3700: DigiKey Part Number: 296-30395-1-ND; MFG: Texas Instruments; PART NUMBER: TPS3700DDCR
U10 = TPS65150_2: DigiKey Part Number: 296-21166-1-ND; MFG: Texas Instruments; PART NUMBER: TPS65150PWPR
U11-U14 = FDV303N: DigiKey Part Number: SI1062X-T1-GE3CT-ND; MFG: Vishay; PART NUMBER: SI1062X-T1-GE3
U15 = BSS84: DigiKey Part Number: 3372-BSS84TR-ND; MFG: NextGen Components
U19 = TLV117118DCYR: DigiKey Part Number: 296-40597-1-ND; MFG: Texas Instruments
U24 U25 = TPS62827DMQ: MFG: Texas Instruments
C86-C89 C113-C124 = C: DigiKey Part Number: 399-11270-1-ND; MFG: KEMET; PART NUMBER: C1210C107M4PAC7800; TOLERANCE: 20%; VOLTAGE: 16V
C91 C92 = CAPACITOR_POL: DigiKey Part Number: 4417PHCT-ND; MFG: Vishay; PART NUMBER: MAL214699603E3; TOLERANCE: 20%; VOLTAGE: 25V
C176 = C: DigiKey Part Number: 399-C0402C181J5GAC7867CT-ND; MFG: KEMET; PART NUMBER: C0402C181J5GAC7867; TOLERANCE: 5%; VOLTAGE: 50V
J9 = 16x1_Header: DigiKey Part Number: S1033E-16-ND; MFG: Sullins
J10 = 3x1_Header: DigiKey Part Number: S1033E-03-ND; MFG: Sullins
R45 = R: DigiKey Part Number: 1276-3480-1-ND; MFG: Samsung; PART NUMBER: RC1005J000CS; TOLERANCE: 1%
R46 R47 = R: DigiKey Part Number: P51.0HCT-ND; MFG: Panasonic; PART NUMBER: ERJ-3EKF51R0V; POWER: 1/10 W; TOLERANCE: 1%
U16 = DLP990U_DMD_SOCKET: MFG: Texas Instruments; Part Number: 2515700
U17 = TMP411: DigiKey Part Number: 2156-ADT7461AR-REEL7-ND; MFG: Analog Devices Inc.; PART NUMBER: ADT7461AR-REEL7
U18 = SN74AUC1G74: DigiKey Part Number: 296-18560-1-ND; MFG: Texas Instruments; PART NUMBER: SN74AUC1G74DCUR
U22 U23 = SN74LVC1G06: DigiKey Part Number: 296-37652-1-ND; MFG: Texas Instruments; MFG PART NUMBER: SN74LVC1G17DBVRG4; PART NUMBER: SN74LVC1G17DBVRG4

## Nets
GND: C1.1 C2.1 C3.1 C4.1 C5.1 C6.1 C17.1 C18.1 C19.1 C20.1 C21.1 C22.1 C23.1 C24.1 C27.2 C28.1 C29.1 C31.2 C33.1 C34.2 C36.2 C37.1 C38.1 C39.1 C40.1 C41.1 C42.1 C43.1 C44.1 C45.1 C46.1 C47.1 C48.1 C49.1 C50.1 C51.1 C52.1 C53.1 C54.1 C55.1 C56.1 C57.1 C58.1 C59.1 C60.1 C61.1 C62.1 C63.1 C64.1 C65.1 C66.1 C67.1 C68.1 C69.1 C70.1 C71.1 C72.1 C73.1 C74.1 C75.1 C76.1 C77.1 C78.1 C79.1 C80.1 C81.1 C82.1 C83.1 C84.1 C85.1 C86.1 C87.1 C88.1 C89.1 C90.1 C91.2 C92.2 C93.1 C94.1 C95.1 C96.1 C97.1 C98.1 C99.1 C100.1 C101.1 C102.1 C103.1 C104.1 C105.1 C106.1 C107.1 C108.1 C109.1 C110.1 C111.1 C112.1 C113.1 C114.1 C115.1 C116.1 C117.1 C118.1 C119.1 C120.1 C121.1 C122.1 C123.1 C124.1 C125.1 C126.1 C127.1 C128.1 C129.1 C130.1 C131.1 C132.1 C133.1 C134.1 C135.1 C136.1 C137.1 C138.1 C139.1 C140.1 C141.1 C142.1 C143.1 C144.1 C145.1 C146.1 C147.1 C148.1 C149.1 C150.1 C151.1 C152.1 C153.1 C154.1 C155.1 C156.1 C157.1 C158.1 C159.1 C160.1 C161.1 C162.1 C163.1 C164.1 C165.1 C166.1 C167.1 C168.1 C169.1 C170.1 C171.1 C172.1 C173.1 C174.1 C175.1 C177.1 C179.1 C181.1 C182.1 C183.1 C184.1 C185.1 C186.1 C187.1 C188.1 C189.1 C190.1 C191.2 C192.1 C193.1 C195.1 C196.1 C197.1 C199.1 C200.1 C201.1 D1.1(ANODE) D6.2(CATHODE) FB3.1 FB4.1 J1.10 J1.13 J1.16 J1.19 J1.20 J1.23 J1.24 J1.27 J1.28 J1.31 J1.32 J1.35 J1.36 J1.39 J1.40 J1.43 J1.44 J1.47 J1.48 J1.51 J1.52 J1.53 J1.54 J1.55 J1.56 J1.57 J1.58 J1.59 J1.60 J1.61 J2.10 J2.13 J2.16 J2.19 J2.20 J2.23 J2.24 J2.27 J2.28 J2.31 J2.32 J2.35 J2.36 J2.39 J2.40 J2.43 J2.44 J2.47 J2.48 J2.51 J2.52 J2.53 J2.54 J2.55 J2.56 J2.57 J2.58 J2.59 J2.60 J2.61 J3.10 J3.13 J3.16 J3.19 J3.20 J3.23 J3.24 J3.27 J3.28 J3.31 J3.32 J3.35 J3.36 J3.39 J3.40 J3.43 J3.44 J3.47 J3.48 J3.51 J3.52 J3.53 J3.54 J3.55 J3.56 J3.57 J3.58 J3.59 J3.60 J3.61 J4.10 J4.13 J4.16 J4.19 J4.20 J4.23 J4.24 J4.27 J4.28 J4.31 J4.32 J4.35 J4.36 J4.39 J4.40 J4.43 J4.44 J4.47 J4.48 J4.51 J4.52 J4.53 J4.54 J4.55 J4.56 J4.57 J4.58 J4.59 J4.60 J4.61 J5.4 R10.1 R19.2 R25.1 R27.1 R29.1 R35.1 R36.2 R42.1 R43.1 R44.1 R57.1 R59.1 R65.1 TP2.1 TP4.1 TP7.1 TP8.1 TP11.1 TP12.1 TP13.1 TP14.1 U6.5(GND) U6.9(Therm_Pad) U7.2(GND) U8.5(VDD) U9.2(GND) U10.7(PGND) U10.8(PGND) U10.11(IN) U10.19(GND) U10.25(Therm_Pad) U12.2(S) U13.2(S) U14.2(S) U15.1(G) U16.A1(VSS) U16.AA3(VSS) U16.AC3(VSS) U16.AC29(VSS) U16.AD2(VSSA) U16.AD6(VSS) U16.AD20(VSS) U16.AE7(VSS) U16.AE9(VSS) U16.AE11(VSS) U16.AE17(VSS) U16.AE21(VSS) U16.AE25(VSS) U16.AE29(VSS) U16.AF8(VSS) U16.AF14(VSS) U16.AF16(VSS) U16.AG3(VSS) U16.AG11(VSS) U16.AG13(VSS) U16.AG15(VSS) U16.AG17(VSS) U16.AG19(VSS) U16.AG21(VSS) U16.AG23(VSS) U16.AG25(VSS) U16.AG27(VSS) U16.AG29(VSS) U16.AH2(VSS) U16.AH4(VSS) U16.AH6(VSS) U16.AH22(VSSA) U16.AH26(VSS) U16.AH28(VSSA) U16.AJ3(VSSA) U16.AJ7(VSSA) U16.AJ9(VSSA) U16.AJ13(VSSA) U16.AJ15(VSSA) U16.AJ17(VSSA) U16.AJ19(VSSA) U16.AJ23(VSSA) U16.AJ25(VSSA) U16.AJ27(VSSA) U16.AK4(VSS) U16.AK6(VSSA) U16.AK8(VSS) U16.AK12(VSSA) U16.AK16(VSSA) U16.AK20(VSSA) U16.AK28(VSSA) U16.AK30(VSS) U16.AL3(VSS) U16.B2(VSSA) U16.B10(VSSA) U16.B28(VSSA) U16.B30(VSSA) U16.C3(VSS) U16.C5(VSSA) U16.C7(VSSA) U16.C9(VSSA) U16.C11(VSSA) U16.C15(VSSA) U16.C17(VSSA) U16.C19(VSSA) U16.C23(VSSA) U16.C25(VSSA) U16.D2(VSS) U16.D22(VSS) U16.D28(VSS) U16.D30(VSS) U16.E3(VSS) U16.E7(VSS) U16.E9(VSSA) U16.E11(VSS) U16.E13(VSS) U16.E15(VSS) U16.E19(VSS) U16.E21(VSS) U16.E25(VSS) U16.E31(VSS) U16.F14(VSS) U16.G3(VSS) U16.G5(VSS) U16.G7(VSS) U16.G9(VSS) U16.G13(VSS) U16.G17(VSS) U16.G19(VSS) U16.G21(VSS) U16.G23(VSS) U16.G25(VSS) U16.G27(VSS) U16.G29(VSS) U16.H2(VSS) U16.H6(VSS) U16.H30(VSS) U16.J3(VSS) U16.J29(VSS) U16.K30(VSS) U16.L29(VSS) U16.M2(VSS) U16.M28(VSS) U16.M30(VSS) U16.N3(VSS) U16.R3(VSS) U16.R29(VSS) U16.T30(VSS) U16.U3(VSS) U16.U29(VSS) U16.V2(VSS) U16.W3(VSS) U16.W29(VSS) U16.Y2(VSS) U17.5(GND) U18.4(GND) U19.2(GND) U19.4(GND_TAB) U22.3(GND) U23.3(GND) U24.4(GND) U25.4(GND)
VDD_DMD: C40.2 C42.2 C43.2 C45.2 C46.2 C47.2 C48.2 C49.2 C50.2 C51.2 C52.2 C53.2 C54.2 C55.2 C56.2 C57.2 C59.2 C60.2 C61.2 C62.2 C63.2 C64.2 C65.2 C66.2 C67.2 C69.2 C70.2 C71.2 C72.2 C73.2 C74.2 C75.2 C76.2 C78.2 C79.2 C80.2 C81.2 C83.2 C84.2 C85.2 C86.2 C87.2 C88.2 C89.2 C91.1 C92.1 C93.2 C95.2 C99.2 C100.2 C101.2 C102.2 C103.2 C104.2 C105.2 C107.2 C109.2 C110.2 C111.2 C112.2 C114.2 C116.2 C117.2 C118.2 C119.2 C120.2 C121.2 C122.2 C125.2 C126.2 C127.2 C129.2 C130.2 C131.2 C132.2 C133.2 C134.2 C143.2 C144.2 C145.2 C146.2 C147.2 C150.2 C151.2 C152.2 C153.2 C154.2 C156.2 C157.2 C164.2 C166.2 C167.2 C171.2 C196.2 C200.2 R58.2 R61.2 TP15.1 U16.A3(VDD) U16.A29(VDD) U16.AA29(VDD) U16.AB4(VDD) U16.AD8(VDD) U16.AD10(VDD) U16.AD12(VDD) U16.AD28(VDD) U16.AE13(VDD) U16.AE15(VDD) U16.AF6(VDD) U16.AF10(VDD) U16.AF12(VDD) U16.AF18(VDD) U16.AF22(VDD) U16.AF24(VDD) U16.AF26(VDD) U16.AF28(VDD) U16.AH10(VDD) U16.AH12(VDD) U16.AH14(VDD) U16.AH16(VDD) U16.AH18(VDD) U16.AJ1(VDD) U16.AJ5(VDD) U16.AJ11(VDD) U16.AJ21(VDD) U16.AJ29(VDD) U16.AJ31(VDD) U16.AK2(VDD) U16.AL29(VDD) U16.B4(VDD) U16.C1(VDD) U16.C13(VDD) U16.C21(VDD) U16.C29(VDD) U16.C31(VDD) U16.D8(VDD) U16.D12(VDD) U16.D16(VDD) U16.D18(VDD) U16.D20(VDD) U16.D24(VDD) U16.F8(VDD) U16.F10(VDD) U16.F12(VDD) U16.F16(VDD) U16.F18(VDD) U16.F20(VDD) U16.H16(VDD) U16.H18(VDD) U16.H20(VDD) U16.H22(VDD) U16.H24(VDD) U16.H28(VDD) U16.K4(VDD) U16.L3(VDD) U16.M4(VDD) U16.N29(VDD) U16.P4(VDD) U16.P28(VDD) U16.T4(VDD) U16.T28(VDD) U16.V4(VDD) U16.V28(VDD) U16.Y28(VDD) U22.5(VCC) U23.5(VCC)
VDDA_DMD: C39.2 C41.2 C44.2 C58.2 C68.2 C77.2 C82.2 C90.2 C94.2 C96.2 C97.2 C98.2 C106.2 C108.2 C113.2 C115.2 C123.2 C124.2 C128.2 C140.2 C141.2 C142.2 C148.2 C149.2 C155.2 C158.2 C159.2 C165.2 C168.2 C169.2 C170.2 C199.2 R62.2 R64.2 TP16.1 U16.AB28(VDDA) U16.AD14(VDDA) U16.AD16(VDDA) U16.AD18(VDDA) U16.AD22(VDDA) U16.AD24(VDDA) U16.AE19(VDDA) U16.AE27(VDDA) U16.AF20(VDDA) U16.AH20(VDDA) U16.AH24(VDDA) U16.D10(VDDA) U16.D14(VDDA) U16.F6(VDDA) U16.G11(VDDA) U16.G15(VDDA) U16.H8(VDDA) U16.H10(VDDA) U16.H12(VDDA) U16.H14(VDDA) U16.H26(VDDA) U16.K28(VDDA)
AMUX_OUT: J8.1 U16.E17(AMUX_OUT)
DCLK_AN: J1.34 U16.N1(DCLK_AN)
DCLK_AP: J1.33 U16.P2(DCLK_AP)
DCLK_BN: J2.34 U16.B18(DCLK_BN)
DCLK_BP: J2.33 U16.A19(DCLK_BP)
DCLK_CN: J3.34 U16.AL11(DCLK_CN)
DCLK_CP: J3.33 U16.AL13(DCLK_CP)
DCLK_DN: J4.34 U16.AH30(DCLK_DN)
DCLK_DP: J4.33 U16.AG31(DCLK_DP)
DD_A0N: J1.18 U16.F2(D_AN<0>)
DD_A0P: J1.17 U16.E1(D_AP<0>)
DD_A1N: J1.22 U16.G1(D_AN<1>)
DD_A1P: J1.21 U16.J1(D_AP<1>)
DD_A2N: J1.26 U16.B6(D_AN<2>)
DD_A2P: J1.25 U16.A5(D_AP<2>)
DD_A3N: J1.30 U16.L1(D_AN<3>)
DD_A3P: J1.29 U16.K2(D_AP<3>)
DD_A4N: J1.38 U16.A7(D_AN<4>)
DD_A4P: J1.37 U16.B8(D_AP<4>)
DD_A5N: J1.42 U16.A9(D_AN<5>)
DD_A5P: J1.41 U16.A11(D_AP<5>)
DD_A6N: J1.46 U16.T2(D_AN<6>)
DD_A6P: J1.45 U16.R1(D_AP<6>)
DD_A7N: J1.50 U16.U1(D_AN<7>)
DD_A7P: J1.49 U16.W1(D_AP<7>)
DD_B0N: J2.18 U16.B12(D_BN<0>)
DD_B0P: J2.17 U16.A13(D_BP<0>)
DD_B1N: J2.22 U16.R31(D_BN<1>)
DD_B1P: J2.21 U16.P30(D_BP<1>)
DD_B2N: J2.26 U16.A15(D_BN<2>)
DD_B2P: J2.25 U16.B14(D_BP<2>)
DD_B3N: J2.30 U16.B16(D_BN<3>)
DD_B3P: J2.29 U16.A17(D_BP<3>)
DD_B4N: J2.38 U16.A21(D_BN<4>)
DD_B4P: J2.37 U16.B20(D_BP<4>)
DD_B5N: J2.42 U16.L31(D_BN<5>)
DD_B5P: J2.41 U16.N31(D_BP<5>)
DD_B6N: J2.46 U16.J31(D_BN<6>)
DD_B6P: J2.45 U16.G31(D_BP<6>)
DD_B7N: J2.50 U16.A23(D_BN<7>)
DD_B7P: J2.49 U16.B22(D_BP<7>)
DD_C0N: J3.18 U16.AL5(D_CN<0>)
DD_C0P: J3.17 U16.AL7(D_CP<0>)
DD_C1N: J3.22 U16.AF2(D_CN<1>)
DD_C1P: J3.21 U16.AG1(D_CP<1>)
DD_C2N: J3.26 U16.AE1(D_CN<2>)
DD_C2P: J3.25 U16.AC1(D_CP<2>)
DD_C3N: J3.30 U16.AB2(D_CN<3>)
DD_C3P: J3.29 U16.AA1(D_CP<3>)
DD_C4N: J3.38 U16.AL9(D_CN<4>)
DD_C4P: J3.37 U16.AK10(D_CP<4>)
DD_C5N: J3.42 U16.AK14(D_CN<5>)
DD_C5P: J3.41 U16.AL15(D_CP<5>)
DD_C6N: J3.46 U16.AL17(D_CN<6>)
DD_C6P: J3.45 U16.AK18(D_CP<6>)
DD_C7N: J3.50 U16.AL21(D_CN<7>)
DD_C7P: J3.49 U16.AL19(D_CP<7>)
DD_D0N: J4.18 U16.AK22(D_DN<0>)
DD_D0P: J4.17 U16.AL23(D_DP<0>)
DD_D1N: J4.22 U16.AK24(D_DN<1>)
DD_D1P: J4.21 U16.AL25(D_DP<1>)
DD_D2N: J4.26 U16.AL27(D_DN<2>)
DD_D2P: J4.25 U16.AK26(D_DP<2>)
DD_D3N: J4.30 U16.U31(D_DN<3>)
DD_D3P: J4.29 U16.V30(D_DP<3>)
DD_D4N: J4.38 U16.AE31(D_DN<4>)
DD_D4P: J4.37 U16.AF30(D_DP<4>)
DD_D5N: J4.42 U16.Y30(D_DN<5>)
DD_D5P: J4.41 U16.W31(D_DP<5>)
DD_D6N: J4.46 U16.AA31(D_DN<6>)
DD_D6P: J4.45 U16.AB30(D_DP<6>)
DD_D7N: J4.50 U16.AC31(D_DN<7>)
DD_D7P: J4.49 U16.AD30(D_DP<7>)
DMD_EN_ARSTZ: J1.9 U23.2(A)
DMD_EN_ARSTZ_BUF: R44.2 U16.AE23(DMD_EN_ARSTZ) U16.E27(DMD_EN_ARSTZ) U16.Y4(DMD_EN_ARSTZ) U23.4(Y)
DMD_PWR_EN: J1.7 J6.2 R10.2 R43.2 R60.1 R63.1 U6.3(ON) U12.1(G) U24.1(EN) U25.1(EN)
DMD_RESERVED: J2.11 U22.2(A)
DMD_RSVD_BUF: R45.2 U22.4(Y)
DMD_TP0: J10.1 U16.AH8(TP0)
DMD_TP1: J10.2 U16.AG7(TP1)
DMD_TP2: J10.3 U16.AG9(TP2)
DMUX_LATCHED: J4.7 U18.5(Q)
DMUX_OUT: J8.2 R57.2 U16.E29(DMUX_OUT) U18.1(CLK)
I2C_SCL_3P3V: J2.14 J5.1 R7.1 U17.8(SCL)
I2C_SDA_3P3V: J2.15 J5.2 R6.1 U17.7(SDA)
LATCH_CLEAR_Z: J4.8 R56.1 U18.6(/CLR)
LS_CLK_N: J1.11 U16.A25(LS_CLK_N)
LS_CLK_P: J1.12 U16.B24(LS_CLK_P)
LS_RDATA_A: J1.8 U16.F24(LS_RDATA_A)
LS_RDATA_B: J2.7 U16.D26(LS_RDATA_B)
LS_RDATA_C: J2.8 U16.F30(LS_RDATA_C)
LS_RDATA_D: J2.9 U16.C27(LS_RDATA_D)
LS_WDATA_N: J1.14 U16.A27(LS_WDATA_N)
LS_WDATA_P: J1.15 U16.B26(LS_WDATA_P)
MBRST0: J9.1 U16.N27(MBRST<0>)
MBRST1: J9.2 U16.R27(MBRST<1>)
MBRST2: J9.3 U16.N5(MBRST<2>)
MBRST3: J9.4 U16.L5(MBRST<3>)
MBRST4: J9.5 U16.L27(MBRST<4>)
MBRST5: J9.6 U16.J27(MBRST<5>)
MBRST6: J9.7 U16.R5(MBRST<6>)
MBRST7: J9.8 U16.J5(MBRST<7>)
MBRST8: J9.9 U16.U27(MBRST<8>)
MBRST9: J9.10 U16.W5(MBRST<9>)
MBRST10: J9.11 U16.AA5(MBRST<10>)
MBRST11: J9.12 U16.W27(MBRST<11>)
MBRST12: J9.13 U16.AC27(MBRST<12>)
MBRST13: J9.14 U16.U5(MBRST<13>)
MBRST14: J9.15 U16.AC5(MBRST<14>)
MBRST15: J9.16 U16.AA27(MBRST<15>)
P1P8V_LDO: C179.2 C181.2 J6.1 R12.2 R53.2 R54.2 R55.2 R56.2 TP17.1 U7.5(VDD) U9.5(VDD) U18.8(VCC)
P3P3V: C1.2 C2.2 C3.2 C4.2 C5.2 C6.2 C17.2 C175.2 C195.2 C197.2 C201.2 J5.3 R1.2 R2.2 R3.2 R4.2 R6.2 R7.2 R9.2 R39.2 R60.2 R63.2 TP1.1 U6.1(VIN) U6.2(VIN) U6.4(VBIAS) U17.1(VCC) U19.1(VIN) U24.6(VIN) U25.6(VIN)
POWERGOOD: D1.2(CATHODE) J2.12 R12.1 R21.2 TP5.1 U7.1(OUTA) U7.6(OUTB) U9.1(OUTA) U9.6(OUTB) U24.2(PG) U25.2(PG)
SW: C26.2 D2.1(ANODE) L2.2 U10.5(SW) U10.6(SW)
V_BIAS: C172.2 C173.2 C174.2 C188.2 C189.2 C190.2 C191.1 C192.2 C193.2 R20.2 R37.2 R50.1 TP10.1 U16.AD4(VBIAS) U16.AE3(VBIAS) U16.D4(VBIAS)
V_BIAS_CPI: C36.1 C37.2 C38.2 D9.2(CATHODE) R41.2 U10.16(CPI)
V_OFFSET: C135.2 C136.2 C137.2 C138.2 C139.2 C182.2 C183.2 C184.2 D7.1(ANODE) R18.2 R31.2 R48.2 TP6.1 U16.AD26(VOFFSET) U16.AE5(VOFFSET) U16.F4(VOFFSET) U16.F26(VOFFSET) U16.H4(VOFFSET)
V_RESET: C160.2 C161.2 C162.2 C163.2 C185.2 C186.2 C187.2 R26.1 R33.2 R49.2 TP9.1 U8.2(GND) U11.2(S) U16.AF4(VRESET) U16.AG5(VRESET) U16.D6(VRESET) U16.E5(VRESET)
N16772038: J4.1 J4.2 J4.3 J4.4 J4.5 J4.6 R4.1
N16773260: J1.1 J1.2 J1.3 J1.4 J1.5 J1.6 R2.1
N16773766: J2.1 J2.2 J2.3 J2.4 J2.5 J2.6 R1.1
N16774650: J3.1 J3.2 J3.3 J3.4 J3.5 J3.6 R3.1
N16775308: FB3.2 J7.3
N16775316: FB4.2 J7.2
N16775420: FB1.2 J7.4
N16775848: FB1.1 FB2.1 R9.1
N16783807: R24.1 R27.2 U9.4(INB-)
N16783825: R20.1 R24.2 U9.3(INA+)
N16783989: R23.1 R26.2 U8.4(INB-)
N16784029: R19.1 R23.2 U8.3(INA+)
N16784057: R21.1 U8.1(OUTA) U8.6(OUTB)
N16784127: R18.1 R22.2 U7.3(INA+)
N16784131: R22.1 R25.2 U7.4(INB-)
N16784325: R39.1 U12.3(D) U13.1(G) U14.1(G) U15.2(S)
N16784355: R37.1 R40.2
N16784357: R40.1 U13.3(D)
N16784417: C19.2 C20.2 C21.2 L2.1 U6.7(VOUT) U6.8(VOUT) U10.4(VIN) U10.13(CTRL) U10.24(FDLY)
N16784489: D8.2(ANODE) U14.3(D)
N16784491: D8.1(CATHODE) R38.1
N16784593: C22.2 C23.2 C24.2 C25.2 C177.2 D2.2(CATHODE) R28.2 R48.1 U10.9(SUP)
N16784602: C25.1 R28.1 R29.2 U10.1(FB)
N16784669: C26.1 D3.2(CATHODE) D4.1(ANODE)
N16784699: C31.1 D4.2(CATHODE) D5.1(ANODE)
N16784701: C30.1 D5.2(CATHODE) D6.1(ANODE)
N16784732: C27.1 C28.2 C29.2 D3.1(ANODE) R30.2 R49.1
N16784789: C30.2 U10.18(DRVN)
N16784866: R30.1 R32.2 U10.21(FBN)
N16784882: C33.2 R32.1 U10.20(REF)
N16784896: C35.2 U10.17(DRVP)
N16784898: R41.1 R42.2 U10.12(FBP)
N16784904: C18.2 U6.6(CT)
N16784908: C35.1 D7.2(CATHODE) D9.1(ANODE)
N16785040: C32.2 R36.1
N16785042: C32.1 U10.22(COMP)
N16785060: C34.1 U10.2(DLY1)
N16795774: R34.2 U11.3(D)
N16795788: R33.1 U11.1(G) U15.3(D)
N16797776: R34.1 R35.2
N16804439: R45.1 U16.F28(RESERVED)
N16806468: R47.2 U17.3(D-)
N16806470: R46.2 U17.2(D+)
N16806960: C176.2 R46.1 U16.F22(TEMP_P)
N16807032: C176.1 R47.1 U16.E23(TEMP_N)
N16928315: R50.2 U10.15(VGH)
N16943816: R53.1 U18.2(D)
N16945352: R54.1 U18.7(/PRE)
N16947306: R55.1 U19.3(VOUT)
N17048439: L3.1 U24.5(SW)
N17048462: C194.2 L3.2 R61.1
N17048467: C194.1 R58.1 R59.2 U24.3(FB)
N17053433: L4.1 U25.5(SW)
N17053437: C198.2 L4.2 R62.1
N17053493: C198.1 R64.1 R65.2 U25.3(FB)
N17736911: R31.1 R38.2
N17782879: FB2.2 J7.1

Not connected (* = marked no-connect by the designer): J3 7* 8* 9* 11* 12* 14* 15*; J4 9* 11* 12* 14* 15*; U10 3(DLY2)* 10(VCOM)* 14(ADJ)* 23(GD)*; U17 4(THERM)* 6(ALERT)*; U18 3(/Q)*; U22 1(NC)*; U23 1(NC)*

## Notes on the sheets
sheet 1
- COMPUTER GENERATED DRAWING - DO NOT REVISE MANUALLY
- REVISIONS
- NOTES, UNLESS OTHERWISE SPECIFIED:
- REV
- DESCRIPTION
- DATE
- APPROVED
- A
- ECO 2172111: Initial Release
- 2/8/2018
- DH
- 1.
  2.
  3.
  4.
  5.
  6.
  7.
  8.
- The netname "P3V3" represents connection to the +3.3V power plane.
  The netname "P1V8" represents connection to the +1.8V power plane.
  The netname "V_OFFSET" represents connection to the +10V power plane.
  The netname "V_RESET" represents connection to the -14V power plane.
  The netname "V_BIAS" represents connection to the +18V power plane.
  The symbol          represents connection to the digital ground plane.
  A "Z" suffix on a signal name indicates an active low signal
  All components with designators "U" are electrostatic discharge sensitive
- B
- Revision B
- 7/15/2019
- DH
- C
- Revision C
- 2/6/2020
- DH
- D
- Revision D
- 6/16/2020
- DH
- E
- Revision E
- 9/24/2021
- DH
- F
- Revision F
- 9/11/2023
- MM
- INDEX
- Rev. B
- Rev. D
- Sheet 1: Cover
  Sheet 2: Front End Interface
  Sheet 3: Power
  Sheet 4: DMD
  Sheet 5: Important Notice
- Changed P1P8V Net Name to VDD_DMD
  Changed R8 Pin 2 connection from P1P8V to P1P8V_LDO
  Changed R5 Pin 2 connection from P1P8V to P1P8V_LDO
  Added net DMUX_LATCHED to J4 Pin 7
  Added net LATCH_CLEAR to J4 Pin 8
  Changed U3 Pin 5 from P1P8V to P1P8V_LDO
  Added pads for R51 and R52 (Components DNI)
  Added C178 (2.2uF) to V_OFFSET
  Changed R12 Pin 2 connection from P1P8V to P1P8V_LDO
  Added U19: 1.8V LDO supply for DLPC980 Logic Ref.
  Added C180 (1uF), C181 (1uF), and R55 (10m) for 1.8V LDO circuit
  Added C177 (2.2u) to V_OFFSET
  Added R48 (10m), R49 (10m), and R50 (10m) - current monitoring resistors
  R29 changed to 63.4k, 1% to adjust V_OFFSET voltage
  R36 changed to 0 ohm to adjust compensation network
  R42 changed to 1%
  V_BIAS circuitry altered:
       The output of the positive charge pump (U10 pin 17) is
       now fed into CPI (U16 pin 16).
       V_BIAS is now output from the VGH pin (U16 pin 15)
  Added C191, C192, and C193 to V_BIAS
  Added C182, C183, C184 (10u) to V_OFFSET (near DMD)
  Added C185, C186, C187 (10u) to V_RESET(near DMD)
  Added C188, C189, C190 (10u) to V_BIAS (near DMD)
  Added U18 to latch DMUX
  Added R53, R54, R56, R57, and C179 for latch circuit
  Added U22 and U23 buffers to account for VDD_DMD variation
- L2 (4.7uH), R36 (0), C25 (36pF), C31 (10uF), and C22 (1uF) devices updated to
  L2 (2.2uH), R36 (56.0K), C25 (47pF), C31 (0.33uF), and C22 (22uF)
- Rev. E
- C18 (1000pF) updated to C18 (4700pF)
  C27 updated to DNI (Do Not Install)
- Rev. F
- Title updated to “ESD, DLPLCR99UVEVM DMD Board for DLP991UUV
  L3 (470uH) and L4 (470uH) footprint update.
         Values of each inductor stays the same, but footprint pads updated.
  Components updated with alternative parts (Footprints remain the same):
     R58, R64  ->  215K resistor replaced with 330K resistor
     D1, D3-D7, D9  -> CUS10S30 updated to PMEG3010 -> Vf updated from .23V to .28V
     D2  -> STPS0540Z updated to CBDW0540 -> Vf updated from .5V to .51V
     D8 -> M3Z3V3B updated to TDZ3V3J,115
     U11 – U14 -> FDY302NZ updated to SI1062X
     U15 -> BSS84 (ONSEMI) updated to BSS84 (MDD)
     U17 -> TMP411 updated to ADT7461, Analog Digital part
- Rev. C
- J6 Pin 1 net changed from VDD_DMD to P1P8V_LDO
  I2C level shifter removed. I2C from DLPC964 now at 3.3V
       U1 removed
       R5, R8 removed
  VDD_DMD and VDDA_DMD Rails Separated
       U2, U3, U4, U5 removed
       FB5, FB6 removed
       L1 removed
       R11, R13, R14, R15, R16, R17, R51, R52 removed
       C7, C8, C9, C10, C11, C12, C13, C14, C15, C16, C178 removed
       TP3 removed
       U24, U25 added
       L3, L4 added
       R58, R59, R60, R61, R62, R63, R64, R65 added
       C194, C195, C196, C197, C198, C199 added
       TP15, TP16 added
       Net VDDA_DMD added
       C39, C41, C44, C58, C68, C77, C82, C90, C94, C96, C97, C98, C106, C108,
            C128, C140, C141, C142, C148, C149, C155, C158, C159, C165, C168, C169,
            C170, C113, C115, C123, C124 changed from VDD_DMD to VDDA_DMD
  Sheet 3 reference to DLPC980 updated to DLPC964 to reflect updated controller name
  L2 (4.7uH), R36 (0), C25 (36pF), C31 (10uF), and C22 (1uF) devices updated to
  L2 (2.2uH), R36 (56.0K), C25 (47pF), C31 (0.33uF), and C22 (22uF)
- Mike McCormick
- 3/17/2023
- 1/26/2023
- 1/26/2023
sheet 2
- Flex Cable 51-pin Connectors to Emulation / ASIC boards
- C
- A
- B
- D
- I2C Level Shifter (Removed)
- Jumper to Enable DMD_PWR
  without connection to ASIC
- 3.3V I2C Connector
- Alternate 3.3V Input
sheet 3
- 3.3V to VDD_DMD (1.9V) at 4A
- DMD Board PowerGood
- 3.3V to VDDA_DMD (1.9V) at 4A
- 1.8V LDO at 1A
  Reference for DLPC964 Logic Level
- DMD Supply Voltages:
  V_OFFSET = 10V
  V_RESET = -14V
  V_BIAS = 18V
- DMD Supply Power Monitors
- Vf = 0.51V
- DMD Supply Power-off Drains
- Vf = 0.28V
- DNI
- 3.3V Zener
sheet 4
- Buffers to account for possible
  variation in VDD_DMD
- DMUX LATCH
- DMD Temperature Sensor
sheet 5
- IMPORTANT NOTICE
